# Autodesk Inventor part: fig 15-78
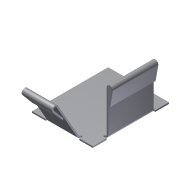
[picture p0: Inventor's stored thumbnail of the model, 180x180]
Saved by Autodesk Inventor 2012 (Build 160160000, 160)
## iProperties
Shininess: 77.0
Angle Display Precision: 2
Document Length Units: 11269
Document Angle Units: 11279
Document Time Units: 11290
Document Mass Units: 11283
Document Length Units Precision: 3
Document Angle Units Precision: 2
Compacted: True
Created: 2002-04
Part Number: fig 15-78
Document SubType Name: Sheet Metal
Density: 1 g/cm^3
Sheet Metal Rule: Default
Material: Default
Density: 0.0
Volumn: 0.0
Area: 0.0
PropertySet Name: Model Information
Control State: 0
Master: False
Checked Out: False
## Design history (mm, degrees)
node "Face1"
  sketch "Sketch1"
    geometry: L1 (-17.882, 11.882)-(2.118, 11.882); L2 (2.118, 11.882)-(2.118, -13.176); L3 (2.118, -13.176)-(-17.882, -13.176); L4 (-17.882, -13.176)-(-17.882, 11.882)
    constraints: 8 end point, 2 parallel, 1 horizontal, 1 perpendicular
    dimensions: "d17" = 20 distance of L2.end L3.end
node "Flange2"
node "Flange3"
feature "Hem8" dims "d82" = 0.5 (= BendReliefWidth), "d83" = 0.25 (= BendReliefDepth), "d84" = 1 (= MinimumRemnant), "d85" = 0.5 (= BendRadius), "d96" = 190 deg, "d97" = 0.5 (= BendRadius), "d98" = 0.5 (= d97), "SeamGap" = 0.01, "Thickness" = 0.5
feature "Hem9" dims "d89" = 0.5 (= BendReliefWidth), "d90" = 0.25 (= BendReliefDepth), "d91" = 1 (= MinimumRemnant), "d92" = 0.5 (= BendRadius), "d99" = 190 deg, "d100" = 0.5 (= BendRadius), "d101" = 0.5 (= d100), "SeamGap" = 0.01, "Thickness" = 0.5
body "Solid1"
face "Plate1" dims "Thickness" = 0.5
sketch "Sketch3"
  geometry: L1 (5, 0)-(20, 0); L2 (20, 0)-(20, 15); L3 (20, 15)-(5, 15); L4 (5, 15)-(5, 0)
  constraints: 8 end point
face "Plate3" dims "d6" = 15, "d7" = 90 deg, "d8" = 0.5 (= BendRadius), "d18" = 5, "d19" = 15, "Thickness" = 0.5, "MinimumRemnant" = 1 (= 2 x Thickness), "BendReliefWidth" = 0.5 (= Thickness)
bend "Bend2" dims "d6" = 15, "d7" = 90 deg, "d8" = 0.5 (= BendRadius), "d56" = 0.5 (= BendReliefWidth), "d57" = 0.25 (= BendReliefDepth), "d58" = 1 (= MinimumRemnant), "SeamGap" = 0.01, "Thickness" = 0.5, "MinimumRemnant" = 1 (= 2 x Thickness), "BendReliefWidth" = 0.5 (= Thickness), "TransitionRadius" = 0.5 (= BendRadius)
sketch "Sketch6"
  geometry: L1 (15, 0)-(5, 0); L2 (5, 0)-(5, 15); L3 (5, 15)-(15, 15); L4 (15, 15)-(15, 0)
  constraints: 8 end point
face "Plate4" dims "d20" = 5, "d21" = 10, "d23" = 15, "d24" = 60 deg, "d25" = 0.5 (= BendRadius), "Thickness" = 0.5, "MinimumRemnant" = 1 (= 2 x Thickness), "BendReliefWidth" = 0.5 (= Thickness)
bend "Bend3" dims "d22" = 0.5 (= BendRadius), "d23" = 15, "d24" = 60 deg, "d25" = 0.5 (= BendRadius), "d59" = 0.5 (= BendReliefWidth), "d60" = 0.25 (= BendReliefDepth), "d61" = 1 (= MinimumRemnant), "SeamGap" = 0.01, "Thickness" = 0.5, "MinimumRemnant" = 1 (= 2 x Thickness), "BendReliefWidth" = 0.5 (= Thickness)
sketch "Sketch12"
  geometry: L1 (0.433, 0.25)-(0, 0); L2 (-0.816, -0.571)-(2.395, -4.398); L3 (2.395, -4.398)-(2.012, -4.719); L4 (2.012, -4.719)-(-1.199, -0.893); A1 r 0.5 centre (-0.433, -0.25) between (0, 0) and (-0.816, -0.571); A2 r 1 centre (-0.433, -0.25) between (0.433, 0.25) and (-1.199, -0.893); 2 further points
  constraints: 8 end point, 4 point on circle
sketch "Sketch13"
  geometry: L1 (0.5, 0)-(0, 0); L2 (-0.992, -0.087)-(-0.125, -5.006); L3 (-0.125, -5.006)-(-0.617, -5.093); L4 (-0.617, -5.093)-(-1.485, -0.174); A1 r 0.5 centre (-0.5, 0) between (0, 0) and (-0.992, -0.087); A2 r 1 centre (-0.5, 0) between (0.5, 0) and (-1.485, -0.174); 2 further points
  constraints: 8 end point, 4 point on circle
other parameters: "BendRadius" = 0.5 (= Thickness), "BendReliefDepth" = 0.25 (= 0.5 x Thickness), "CornerReliefSize" = 2 (= 4 x Thickness), "d0" = 0.5 (= BendRadius), "d5" = 0.5 (= BendRadius), "d26" = 0.5 (= BendRadius), "d30" = 0.5 (= BendRadius), "JacobiRadiusSize" = 0.5 (= Thickness), "GapSize" = 0.5 (= Thickness)
